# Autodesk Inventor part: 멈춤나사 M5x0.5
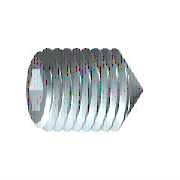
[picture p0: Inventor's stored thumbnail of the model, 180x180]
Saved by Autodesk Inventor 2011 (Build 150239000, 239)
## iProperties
Company: 한국ATC센터
IsCustomPart: 1
Created: 2014-11
Part Number: 멈춤나사 M5x0.5
Material: 강, 연강
Description: 6각 소켓 머리 없는 멈춤 나사
Document SubType Name: Modeling
Standard: KS B 1028
Designer: KYOUNG IL JANG
Standards Organization: KS
Language: ko-KR
Size Designation: 원추점 M5x10
Categories: <MemberInstance><Categories><Category DisplayName="조임쇠" InternalName="e4da775c-781d-43d5-af7c-5136215cf5a6" Mnemonic="FSTN"><Category DisplayName="볼트" InternalN
Density: 7.86 g/cm^3
Mass: 1.16912 g
Surface Area: 1.91683 cm^2
Volume: 0.148743 cm^3
Author: KYOUNG IL JANG
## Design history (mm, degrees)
revolve "본체" stored, may be unused: angle "d6" = 90 deg
sketch "스케치2"
  geometry: L1 (-0.722, 1.25)-(0.722, 1.25); L2 (0.722, 1.25)-(1.443, 0); L3 (1.443, 0)-(0.722, -1.25); L4 (0.722, -1.25)-(-0.722, -1.25); L5 (-0.722, -1.25)-(-1.443, 0); L6 (-1.443, 0)-(-0.722, 1.25); 3 further points
  constraints: 12 end point, 1 coincident, 1 horizontal, 13 other
extrude "슬롯" join sketch "스케치2" taper "d7" = 0 deg; stored distance "d21" = 10
workaxis "Work Axis1"
workplane "Work Plane1"
body "Solid1"
feature "스레드" dims "d12" = 10 (= NLG), "d13" = 0
chamfer "모따기1" distance "d8" = 2.25 (computed from NND, SPD, FAWI); stored, may be unused: angle "d9" = 45 deg (= FAWI), second distance "d34" = 2.25 (computed from NND, SPD, FAWI)
chamfer "모따기2" distance "d10" = 0.49076 (= -0.5 x GD1 + 0.5 x NND); stored, may be unused: angle "d11" = 45 deg (= FAWI), second distance "d35" = 0.49076 (= -0.5 x GD1 + 0.5 x NND)
sketch "스케치1"
  geometry: L1 (0, 0)-(6.167, 0); L2 (10, 1.443)-(10, 2.5); L3 (10, 2.5)-(0, 2.5); L4 (10, 1.443)-(7, 1.443); L5 (7, 1.443)-(6.167, 0); L6 (0, -0.5)-(0, 3) reference; L7 (0, 2.5)-(0, 0)
  constraints: 13 end point, 3 parallel, 1 collinear, 1 perpendicular, 1 point on line
  dimensions: "d0" = 3 distance of L2.start L4.end (= INTI); "d1" = 60 deg angle of L5 L1; "d2" = 5 diameter of L3 L1 (= NND); "d3" = 2.88675 diameter of L4 L1 (= 1.1547 x SW); "d5" = 10 distance from line of L2 L3.end (= NLG)
other parameters: "NND" = 5 [user parameter; used in 5 equation terms], "NLG" = 10 [user parameter; used in 2 equation terms], "INTI" = 3 [user parameter; used in 1 equation term], "FAWI" = 45 deg [user parameter; used in 4 equation terms], "SW" = 2.5 [user parameter; used in 2 equation terms], "GD1" = 4.01848 (= THREADDIA - 1.2269 x PTC) [user parameter; used in 2 equation terms], "d4" = 0, "FAWI1" = 45 deg [user parameter], "SPD" = 0.5 [user parameter; used in 2 equation terms], "d36" = 0, "d37" = 0, "GUL" = 0.49076 (= 0.61345 x PTC) [user parameter], "TPU" = 12.5 (computed from PTC) [user parameter], "TOA" = 30 deg [user parameter], "THREADDIA" = 5 [user parameter; used in 1 equation term], "PTC" = 0.8 [user parameter; used in 4 equation terms], "GAL" = 0.49076 (= 0.61345 x PTC) [user parameter], "E0" = 2.8875 (= 1.155 x SW) [user parameter]
